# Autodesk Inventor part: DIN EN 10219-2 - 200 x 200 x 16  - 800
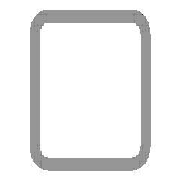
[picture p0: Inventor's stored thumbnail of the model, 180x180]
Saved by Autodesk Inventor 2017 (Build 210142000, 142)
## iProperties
Created: 2017-11
Part Number: DIN EN 10219-2 - 200 x 200 x 16  - 800
Material: Steel, Mild
Description: Cold formed welded structural hollow sections of non-alloy and fine grain structural steel
Document SubType Name: Modeling
Standard: DIN
Designer: iusti
Standard Revision: 2006-07
Standards Organization: DIN
Language: en-US
Size Designation: 200 x 200 x 16
Categories: <MemberInstance><Categories><Category DisplayName="Structural Shapes" InternalName="089c4875-fa83-4c05-b084-43b9cc11f5ed" Mnemonic="GRDR"><CategoryParameter Dis
Stock Number: 200 x 200 x 16
Mass: 67053.1 g
Surface Area: 10890.8 cm^2
Volume: 8541.79 cm^3
Density: 7.85 g/cm^3
Appearance: Semi-Polished
IsCustomPart: 1
_CCFamilyMember: 103
_CCFamilyDisplayName: DIN EN 10219-2 (Square Hollow Section - Cold Formed) - Cold formed welded structural hollow sections of non-alloy and fine grain structural steel
_FrameMemberDoc: Frame Member File
_Version: 15.0.0
_GetPNFromCC: 1
Author: iusti
G_L: 800.000 mm
G_W: 200.000 mm
G_H: 200.000 mm
+283E1D8B-273E-42A8-8E91-D86861E19284+CUTDETAIL1: Cut
+7AC7364C-9462-4BE7-8F37-816BA4E0C8A9+CUTDETAIL2: Cut
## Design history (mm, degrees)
node "Start plane"
node "End plane"
sketch "Sketch"
  geometry: L1 (-100, -52)-(-100, 52); L2 (-52, 100)-(52, 100); L3 (100, 52)-(100, -52); L4 (52, -100)-(-52, -100); L5 (-52, 84)-(52, 84); L6 (84, 52)-(84, -52); L7 (52, -84)-(-52, -84); L8 (-84, -52)-(-84, 52); L9 (0, 153.918)-(0, -153.918) reference; L10 (-153.918, 0)-(153.918, 0) reference; A1 r 48 centre (-52, -52) between (-100, -52) and (-52, -100); A2 r 48 centre (-52, 52) between (-52, 100) and (-100, 52); A3 r 48 centre (52, 52) between (100, 52) and (52, 100); A4 r 48 centre (52, -52) between (52, -100) and (100, -52); A5 r 32 centre (-52, 52) between (-52, 84) and (-84, 52); A6 r 32 centre (52, 52) between (84, 52) and (52, 84); A7 r 32 centre (52, -52) between (52, -84) and (84, -52); A8 r 32 centre (-52, -52) between (-84, -52) and (-52, -84)
  constraints: 16 end point, 16 point on circle, 8 centre point, 8 tangent, 4 parallel, 3 equal radius, 2 perpendicular, 7 other
  dimensions: "d7" = 48 radius of A1 (= G_IR); "d10" = 200 distance between parallel lines of L2 L4 (= G_H); "d11" = 200 distance between parallel lines of L1 L3 (= G_W); "d12" = 16 distance between parallel lines of L3 L6 (= G_T); "d15" = 100 distance between parallel lines of L2 L10 (= 0.5 x d10); "d16" = 100 distance between parallel lines of L9 L3 (= 0.5 x d11)
extrude "Body" new body sketch "Sketch" stored distance "d3" = 800 (= G_L); taper "d4" = 0 deg
node "Driven Length"
  sketch "Sketch3"
    geometry: L1 (0, 0)-(10, 0) reference
    constraints: 2 end point, 1 horizontal
  workplane "Work Plane3"
  sketch "Sketch4"
    geometry: L1 (-2, 100)-(12, 100) reference; L2 (-2, 900)-(12, 900) reference
    dimensions: "d18" = 800 distance between parallel lines of L1 L2 (derived)
workplane "Work Plane4"
split "Split1"
workplane "Work Plane5"
split "Split2"
body "Solid1"
other parameters: "G_W" = 200 [user parameter; used in 1 equation term], "G_H" = 200 [user parameter; used in 1 equation term], "G_T" = 16 [user parameter; used in 1 equation term], "G_IR" = 48 [user parameter; used in 1 equation term], "G_L" = 800 (= d18) [user parameter; used in 1 equation term], "d17" = 90 deg
